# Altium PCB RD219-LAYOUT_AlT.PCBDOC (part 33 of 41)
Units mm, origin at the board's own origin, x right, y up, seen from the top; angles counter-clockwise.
Board outline 209.75 x 159.97 mm, 2 copper layers (TOP, BOTTOM), stack 0 mm thick; 398 components, 199 nets, 1469 pads, 0 vias.
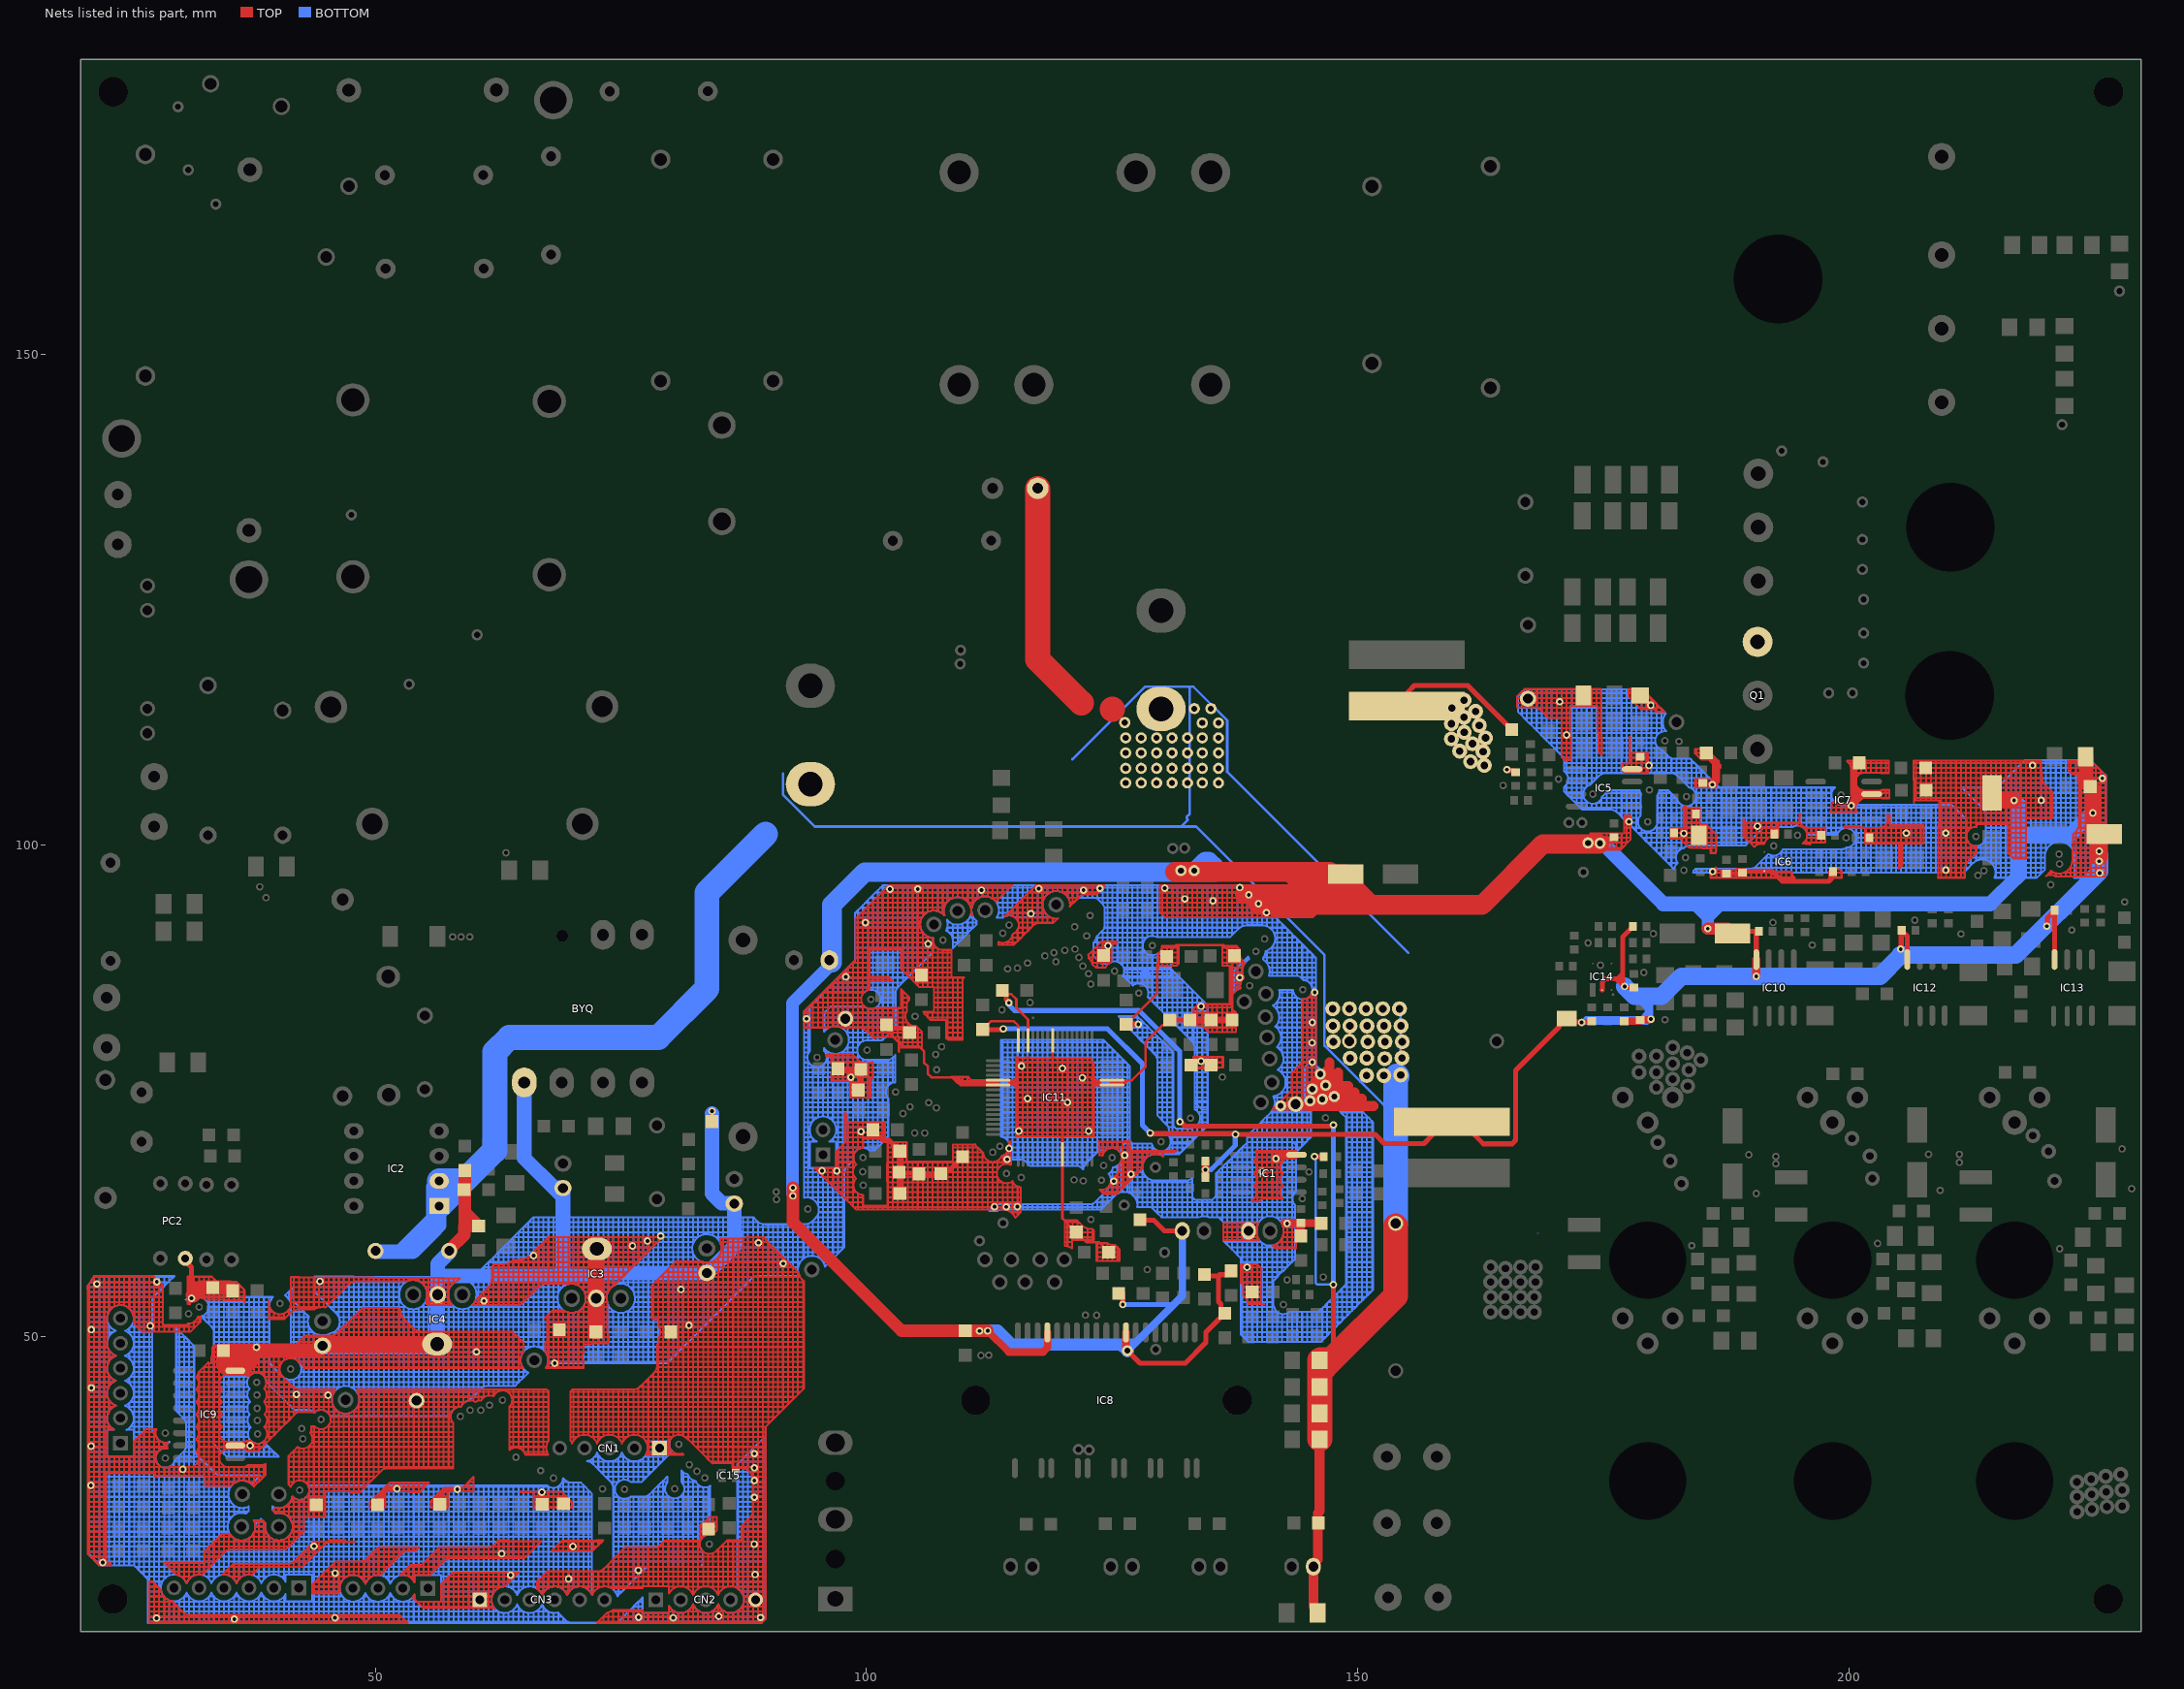
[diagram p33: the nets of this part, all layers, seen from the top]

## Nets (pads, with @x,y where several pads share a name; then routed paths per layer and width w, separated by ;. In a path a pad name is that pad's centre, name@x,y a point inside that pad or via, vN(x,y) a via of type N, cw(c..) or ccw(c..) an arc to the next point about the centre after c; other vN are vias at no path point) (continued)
GND: (continued)
  BOTTOM w0.203: 131.125,68.586 131.125,68.768 ; 131.125,68.586 131.633,68.586 ; 131.125,68.768 131.125,69.276 ; 131.125,68.768 131.252,68.641 131.633,68.641 ; 131.125,68.768 131.633,68.768 ; 131.125,69.276 131.633,69.276 ; 131.125,69.276 131.125,69.657 ; 131.125,69.657 131.125,69.784 ; 131.125,69.657 131.633,69.657 ; 131.125,69.784 131.125,70.292 ; 131.125,69.784 131.633,69.784 ; 131.125,70.292 131.125,70.8 ; 131.125,70.292 131.633,70.292 ; 131.125,70.8 131.633,70.8 ; 131.125,70.8 131.125,71.308 ; 131.125,71.308 131.125,71.816 ; 131.125,71.308 131.379,71.308 ; 131.125,71.816 131.125,72.324 ; 131.125,71.816 131.252,71.816 ; 131.125,72.324 131.125,72.832 ; 131.125,72.324 131.252,72.324 ; 131.125,72.832 131.125,73.34 ; 131.125,72.832 131.252,72.832 ; 131.125,73.34 131.125,73.848 ; 131.125,73.34 131.252,73.34 ; 131.125,73.848 131.125,74.356 ; 131.125,73.848 131.252,73.848 ; 131.125,74.356 131.125,74.864 ; 131.125,74.356 131.252,74.356 ; 131.125,74.864 131.125,75.372 ; 131.125,74.864 131.252,74.864 ; 131.125,75.372 131.125,75.88 ; 131.125,75.372 131.252,75.372 ; 131.125,75.88 131.125,76.388 ; 131.125,75.88 131.252,75.88 ; 131.125,76.388 131.125,76.896 ; 131.125,76.388 131.252,76.388 ; 131.125,76.896 131.125,77.404 ; 131.125,76.896 131.252,76.896 ; 131.125,77.404 131.125,77.912 ; 131.125,77.404 131.252,77.404 ; 131.125,77.912 131.252,77.912 ; 131.125,77.912 131.125,78.42 ; 131.125,78.42 131.252,78.42 ; 131.125,78.42 131.125,78.928 ; 131.125,78.928 131.252,78.928 ; 131.125,78.928 131.125,79.055 ; 131.125,79.055 131.252,78.928 ; 131.125,82.06 131.209,81.976 ; 131.125,82.06 131.125,82.484 ; 131.125,82.484 131.125,82.992 ; 131.125,82.484 131.633,82.484 ; 131.125,82.992 131.125,83.5 ; 131.125,82.992 131.633,82.992 ; 131.125,83.5 131.125,84.008 ; 131.125,83.5 131.633,83.5 ; 131.125,84.008 131.125,84.516 ; 131.125,84.008 131.633,84.008 ; 131.125,84.516 131.633,84.516 ; 131.125,84.516 131.125,85.024 ; 131.125,85.024 131.125,85.532 ; 131.125,85.024 131.633,85.024 ; 131.125,85.532 131.125,86.04 ; 131.125,85.532 131.633,85.532 ; 131.125,86.04 131.125,86.548 ; 131.125,86.04 131.633,86.04 ; 131.125,86.548 131.125,87.056 ; 131.125,86.548 131.633,86.548 ; 131.125,87.056 131.379,87.056 ; 131.125,87.056 131.125,87.31 ; 131.125,87.31 131.379,87.056 ; 131.125,90.655 131.125,91.12 ; 131.125,90.655 131.633,90.655 ; 131.125,91.12 131.125,91.628 ; 131.125,91.12 131.633,91.12 ; 131.125,91.628 131.125,92.136 ; 131.125,91.628 131.633,91.628 ; 131.125,92.136 131.125,92.644 ; 131.125,92.136 131.633,92.136 ; 131.125,92.644 131.125,93.152 ; 131.125,92.644 131.633,92.644 ; 131.125,93.152 131.125,93.66 ; 131.125,93.152 131.633,93.152 ; 131.125,93.66 131.125,94.168 ; 131.125,93.66 131.633,93.66 ; 131.125,94.168 131.125,94.676 ; 131.125,94.168 131.633,94.168 ; 131.125,94.676 131.125,95.184 ; 131.125,94.676 131.633,94.676 ; 131.125,95.184 131.125,95.692 ; 131.125,95.184 131.633,95.184 ; 131.125,95.692 131.125,95.946 ; 131.125,95.692 131.633,95.692 ; 131.125,95.946 131.633,95.946 ; 131.209,81.976 131.633,81.552 ; 131.209,81.976 131.633,81.976 ; 131.252,71.816 131.252,72.324 ; 131.252,71.816 131.252,71.435 131.379,71.308 ; 131.252,72.324 131.252,72.832 ; 131.252,72.832 131.252,73.34 ; 131.252,73.34 131.252,73.848 ; 131.252,73.848 131.252,74.356 ; 131.252,74.356 131.252,74.864 ; 131.252,74.864 131.252,75.372 ; 131.252,75.372 131.252,75.88 ; 131.252,75.88 131.252,76.388 ; 131.252,76.388 131.252,76.896 ; 131.252,76.896 131.252,77.404 ; 131.252,77.404 131.252,77.912 ; 131.252,77.912 131.252,78.42 ; 131.252,78.42 131.252,78.928 ; 131.379,71.308 131.506,71.181 131.633,71.181 ; 131.379,87.056 131.633,86.802 ; 131.633,62.164 131.633,62.672 ; 131.633,62.164 132.141,62.164 ; 131.633,62.672 131.633,63.18 ; 131.633,62.672 132.141,62.672 ; 131.633,63.18 131.633,63.688 ; 131.633,63.18 132.141,63.18 ; 131.633,63.688 131.633,64.196 ; 131.633,63.688 132.141,63.688 ; 131.633,64.196 131.633,64.704 ; 131.633,64.196 132.141,64.196 ; 131.633,64.704 131.633,65.212 ; 131.633,64.704 132.141,64.704 ; 131.633,65.212 131.633,65.72 ; 131.633,65.212 132.141,65.212 ; 131.633,65.72 131.633,65.882 ; 131.633,65.72 132.141,65.72 ; 131.633,65.882 132.141,65.882 ; 131.633,68.586 131.633,68.641 ; 131.633,68.586 131.832,68.586 132.713,69.466 ; 131.633,68.641 131.633,68.768 ; 131.633,68.641 131.887,68.641 132.014,68.768 ; 131.633,68.768 131.633,69.276 ; 131.633,68.768 132.014,68.768 ; 131.633,69.276 132.141,69.276 ; 131.633,69.276 131.633,69.657 ; 131.633,69.657 131.633,69.784 ; 131.633,69.657 132.141,69.657 ; 131.633,69.784 131.633,70.292 ; 131.633,69.784 132.141,69.784 ; 131.633,70.292 131.633,70.8 ; 131.633,70.292 132.141,70.292 ; 131.633,70.8 132.141,70.8 ; 131.633,70.8 131.633,71.181 ; 131.633,71.181 132.141,71.181 ; 131.633,81.552 131.717,81.468 ; 131.633,81.552 131.633,81.976 ; 131.633,81.976 131.633,82.484 ; 131.633,81.976 132.141,81.976 ; 131.633,82.484 131.633,82.992 ; 131.633,82.484 132.141,82.484 ; 131.633,82.992 131.633,83.5 ; 131.633,82.992 132.141,82.992 ; 131.633,83.5 131.633,84.008 ; 131.633,83.5 132.141,83.5 ; 131.633,84.008 131.633,84.516 ; 131.633,84.008 132.141,84.008 ; 131.633,84.516 131.633,85.024 ; 131.633,84.516 132.141,84.516 ; 131.633,85.024 131.633,85.532 ; 131.633,85.024 132.141,85.024 ; 131.633,85.532 131.633,86.04 ; 131.633,85.532 132.141,85.532 ; 131.633,86.04 131.633,86.548 ; 131.633,86.04 132.141,86.04 ; 131.633,86.548 131.633,86.802 ; 131.633,86.548 131.887,86.548 ; 131.633,86.802 131.887,86.548 ; 131.633,90.655 131.633,91.12 ; 131.633,90.655 132.141,90.655 ; 131.633,91.12 131.633,91.628 ; 131.633,91.12 132.141,91.12 ; 131.633,91.628 131.633,92.136 ; 131.633,91.628 132.141,91.628 ; 131.633,92.136 131.633,92.644 ; 131.633,92.136 132.141,92.136 ; 131.633,92.644 131.633,93.152 ; 131.633,92.644 132.141,92.644 ; 131.633,93.152 131.633,93.66 ; 131.633,93.152 132.141,93.152 ; 131.633,93.66 131.633,94.168 ; 131.633,93.66 132.141,93.66 ; 131.633,94.168 131.633,94.676 ; 131.633,94.168 132.141,94.168 ; 131.633,94.676 131.633,95.184 ; 131.633,94.676 pad.@132.141,94.676 ; 131.633,95.184 131.633,95.692 ; 131.633,95.184 132.141,95.184 ; 131.633,95.692 131.633,95.946 ; 131.633,95.692 132.141,95.692 ; 131.633,95.946 132.141,95.946 ; 131.717,81.468 132.141,81.044 ; 131.717,81.468 132.141,81.468 ; 131.887,86.548 132.141,86.294 ; 132.014,68.768 132.141,68.895 ; 132.141,62.164 132.141,62.672 ; 132.141,62.164 132.649,62.164 ; 132.141,62.672 132.141,63.18 ; 132.141,62.672 132.649,62.672 ; 132.141,63.18 132.141,63.688 ; 132.141,63.18 132.649,63.18 ; 132.141,63.688 132.141,64.196 ; 132.141,63.688 132.649,63.688 ; 132.141,64.196 132.141,64.704 ; 132.141,64.196 132.649,64.196 ; 132.141,64.704 132.141,65.212 ; 132.141,64.704 132.649,64.704 ; 132.141,65.212 132.141,65.72 ; 132.141,65.212 132.649,65.212 ; 132.141,65.72 132.141,65.882 ; 132.141,65.72 132.649,65.72 ; 132.141,65.882 132.392,65.882 ; 132.141,68.895 132.649,69.403 ; 132.141,68.895 132.141,69.276 ; 132.141,69.276 132.141,69.657 ; 132.141,69.657 132.141,69.784 ; 132.141,69.657 132.522,69.657 132.649,69.53 ; 132.141,69.784 132.141,70.292 ; 132.141,69.784 132.649,69.784 ; 132.141,70.292 132.141,70.8 ; 132.141,70.292 132.649,70.292 ; 132.141,70.8 132.649,70.8 ; 132.141,70.8 132.141,71.181 ; 132.141,71.181 132.649,71.181 ; 132.141,81.044 132.225,80.96 ; 132.141,81.044 132.141,81.468 ; 132.141,81.468 132.141,81.976 ; 132.141,81.468 132.649,81.468 ; 132.141,81.976 132.141,82.484 ; 132.141,81.976 132.649,81.976 ; 132.141,82.484 132.141,82.992 ; 132.141,82.484 132.649,82.484 ; 132.141,82.992 132.141,83.5 ; 132.141,82.992 132.649,82.992 ; 132.141,83.5 132.141,84.008 ; 132.141,83.5 132.649,83.5 ; 132.141,84.008 132.141,84.516 ; 132.141,84.008 132.649,84.008 ; 132.141,84.516 132.141,85.024 ; 132.141,84.516 132.649,84.516 ; 132.141,85.024 132.141,85.532 ; 132.141,85.024 132.649,85.024 ; 132.141,85.532 132.141,86.04 ; 132.141,85.532 132.649,85.532 ; 132.141,86.04 132.141,86.294 ; 132.141,86.04 132.395,86.04 ; 132.141,86.294 132.395,86.04 ; 132.141,90.655 132.141,91.12 ; 132.141,90.655 132.649,90.655 ; 132.141,91.12 132.141,91.628 ; 132.141,91.12 132.649,91.12 ; 132.141,91.628 132.141,92.136 ; 132.141,91.628 132.649,91.628 ; 132.141,92.136 132.141,92.644 ; 132.141,92.136 132.649,92.136 ; 132.141,92.644 132.141,93.152 ; 132.141,92.644 132.649,92.644 ; 132.141,93.152 132.141,93.66 ; 132.141,93.152 132.649,93.152 ; 132.141,93.66 132.141,94.168 ; 132.141,93.66 132.649,93.66 ; 132.141,94.168 pad.@132.141,94.676 ; 132.141,94.168 132.649,94.168 ; pad.@132.141,94.676 132.141,95.184 ; pad.@132.141,94.676 pad.@132.649,94.676 ; 132.141,95.184 132.141,95.692 ; 132.141,95.184 132.649,95.184 ; 132.141,95.692 132.141,95.946 ; 132.141,95.692 132.649,95.692 ; 132.141,95.946 132.649,95.946 ; 132.225,80.96 132.649,80.536 ; 132.225,80.96 132.649,80.96 ; 132.392,65.882 ccw(c132.392,67.234) 132.649,65.907 ; 132.392,65.882 ccw(c132.392,67.234) 132.649,65.907 ; 132.395,86.04 132.649,85.786 ; 132.649,62.164 133.157,62.164 ; 132.649,62.164 132.649,62.672 ; 132.649,62.672 133.157,62.672 ; 132.649,62.672 132.649,63.18 ; 132.649,63.18 133.157,63.18 ; 132.649,63.18 132.649,63.688 ; 132.649,63.688 132.649,64.196 ; 132.649,63.688 133.157,63.688 ; 132.649,64.196 133.157,64.196 ; 132.649,64.196 132.649,64.704 ; 132.649,64.704 133.157,64.704 ; 132.649,64.704 132.649,65.212 ; 132.649,65.212 133.157,65.212 ; 132.649,65.212 132.649,65.72 ; 132.649,65.72 133.157,65.72 ; 132.649,65.72 132.649,65.907 ; 132.649,69.403 132.713,69.466 ; 132.649,69.403 132.649,69.53 ; 132.649,69.53 132.649,69.784 ; 132.649,69.53 132.713,69.466 ; 132.649,69.784 132.649,70.292 ; 132.649,70.292 132.649,70.8 ; 132.649,70.292 133.157,70.292 ; 132.649,70.8 133.157,70.8 ; 132.649,70.8 132.649,71.181 ; 132.649,80.536 132.733,80.452 ; 132.649,80.536 132.649,80.96 ; 132.649,80.96 133.157,80.96 ; 132.649,80.96 132.649,81.468 ; 132.649,81.468 133.157,81.468 ; 132.649,81.468 132.649,81.976 ; 132.649,81.976 133.157,81.976 ; 132.649,81.976 132.649,82.484 ; 132.649,82.484 133.157,82.484 ; 132.649,82.484 132.649,82.992 ; 132.649,82.992 133.157,82.992 ; 132.649,82.992 132.649,83.5 ; 132.649,83.5 132.649,84.008 ; 132.649,83.5 133.157,83.5 ; 132.649,84.008 132.649,84.516 ; 132.649,84.008 133.157,84.008 ; 132.649,84.516 133.157,84.516 ; 132.649,84.516 132.649,85.024 ; 132.649,85.024 132.649,85.532 ; 132.649,85.024 133.157,85.024 ; 132.649,85.532 132.649,85.786 ; 132.649,85.532 132.903,85.532 ; 132.649,85.786 132.903,85.532 ; 132.649,90.655 132.649,91.12 ; 132.649,90.655 133.157,90.655 ; 132.649,91.12 132.649,91.628 ; 132.649,91.12 133.157,91.12 ; 132.649,91.628 132.649,92.136 ; 132.649,91.628 133.157,91.628 ; 132.649,92.136 132.649,92.644 ; 132.649,92.136 133.157,92.136 ; 132.649,92.644 132.649,93.152 ; 132.649,92.644 133.157,92.644 ; 132.649,93.152 132.649,93.66 ; 132.649,93.152 133.157,93.152 ; 132.649,93.66 132.649,94.168 ; 132.649,93.66 133.157,93.66 ; 132.649,94.168 133.157,94.168 ; 132.649,94.168 pad.@132.649,94.676 ; pad.@132.649,94.676 132.649,95.184 ; pad.@132.649,94.676 133.157,94.676 ; 132.649,95.184 132.649,95.692 ; 132.649,95.184 133.157,95.184 ; 132.649,95.692 132.649,95.946 ; 132.649,95.692 133.157,95.692 ; 132.649,95.946 133.157,95.946 ; 132.713,69.466 134.726,71.48 134.726,71.816 ; 132.733,80.452 133.157,80.452 ; 132.903,85.532 133.157,85.278 ; 133.157,62.164 133.665,62.164 ; 133.157,62.164 133.157,62.672 ; 133.157,62.672 133.665,62.672 ; 133.157,62.672 133.157,63.18 ; 133.157,63.18 133.665,63.18 ; 133.157,63.18 133.157,63.688 ; 133.157,63.688 133.157,64.196 ; 133.157,63.688 133.665,63.688 ; 133.157,64.196 133.157,64.704 ; 133.157,64.196 133.157,64.704 ; 133.157,64.196 133.411,63.942 133.665,63.942 ; 133.157,64.704 133.157,65.212 ; 133.157,64.704 133.157,65.212 ; 133.157,65.212 133.157,65.72 ; 133.157,65.212 133.157,65.72 ; 133.157,65.72 133.157,66.12 ; 133.157,65.72 133.157,66.12 ; 133.157,66.12 cw(c132.392,67.234) 132.65,65.907 ccw(c132.392,67.234) 133.157,66.12 ; 133.157,66.12 ccw(c132.392,67.234) 133.167,66.127 cw(c132.392,67.234) 133.157,66.12 ; 133.157,70.292 133.157,70.8 ; 133.157,70.8 133.665,70.8 ; 133.157,70.8 133.157,71.28 ; 133.157,71.28 ccw(c132.977,72.246) 133.269,71.308 ; 133.157,80.452 133.157,80.96 ; 133.157,80.452 133.157,80.026 133.157,80.452 ; 133.157,80.452 133.157,80.96 ; 133.157,80.96 133.157,81.468 ; 133.157,80.96 133.157,81.468 ; 133.157,81.468 133.157,81.976 ; 133.157,81.468 133.157,81.976 ; 133.157,81.976 133.157,82.484 ; 133.157,81.976 133.157,82.484 ; 133.157,82.484 133.157,82.992 ; 133.157,82.484 133.157,82.992 ; 133.157,82.992 133.157,83.5 ; 133.157,82.992 133.284,83.119 ; 133.157,83.5 133.157,84.008 ; 133.157,83.5 133.665,83.5 ; 133.157,84.008 133.157,84.516 ; 133.157,84.008 133.665,84.008 ; 133.157,84.516 133.665,84.516 ; 133.157,84.516 133.157,85.024 ; 133.157,85.024 133.157,85.278 ; 133.157,85.024 133.411,85.024 ; 133.157,85.278 133.411,85.024 ; 133.157,90.655 133.157,91.12 ; 133.157,90.655 133.665,90.655 ; 133.157,91.12 133.157,91.628 ; 133.157,91.12 133.665,91.12 ; 133.157,91.628 133.157,92.136 ; 133.157,91.628 133.665,91.628 ; 133.157,92.136 133.157,92.644 ; 133.157,92.136 133.665,92.136 ; 133.157,92.644 133.157,93.152 ; 133.157,92.644 133.665,92.644 ; 133.157,93.152 133.157,93.66 ; 133.157,93.152 133.665,93.152 ; 133.157,93.66 133.157,94.168 ; 133.157,93.66 133.665,93.66 ; 133.157,94.168 133.157,94.676 ; 133.157,94.168 133.665,94.168 ; 133.157,94.676 133.157,95.184 ; 133.157,94.676 133.665,94.676 ; 133.157,95.184 133.157,95.692 ; 133.157,95.184 133.665,95.184 ; 133.157,95.692 133.157,95.946 ; 133.157,95.692 133.665,95.692 ; 133.157,95.946 133.665,95.946 ; 133.269,71.308 ccw(c132.977,72.246) 133.665,71.545 ; 133.269,71.308 133.665,71.308 ; 133.284,79.944 133.284,80.452 ; 133.284,79.944 133.665,79.944 ; 133.284,80.452 133.665,80.452 ; 133.284,80.452 133.284,80.96 ; 133.284,80.96 133.665,80.96 ; 133.284,80.96 133.284,81.468 ; 133.284,81.468 133.284,81.976 ; 133.284,81.468 133.665,81.468 ; 133.284,81.976 133.284,82.484 ; 133.284,81.976 133.665,81.976 ; 133.284,82.484 133.284,82.992 ; 133.284,82.484 133.665,82.484 ; 133.284,82.992 133.284,83.119 ; 133.284,82.992 133.665,82.992 ; 133.284,83.119 133.665,83.119 ; 133.411,85.024 133.665,84.77 ; 133.423,79.436 cw(c132.573,79.339) 133.429,79.339 ; 133.423,79.436 cw(c132.573,79.339) 133.429,79.339 ; 133.423,79.436 ccw(c132.573,79.339) 133.328,79.741 cw(c132.573,79.339) 133.423,79.436 ; 133.423,79.436 133.665,79.436 ; 133.429,73.118 cw(c132.977,72.246) 133.665,72.947 ; 133.429,73.118 133.429,73.34 ; 133.429,73.34 133.429,73.83 ; 133.429,73.34 133.665,73.34 ; 133.429,73.83 133.429,73.848 ; 133.429,73.83 133.665,73.594 ; 133.429,73.848 133.429,73.975 ; 133.429,73.848 133.665,73.848 ; 133.429,73.975 133.429,74.356 ; 133.429,73.975 133.665,73.975 ; 133.429,74.356 133.665,74.356 ; 133.429,74.356 133.429,74.864 ; 133.429,74.864 133.665,74.864 ; 133.429,74.864 133.429,75.372 ; 133.429,75.372 133.665,75.372 ; 133.429,75.372 133.429,75.88 ; 133.429,75.88 133.665,75.88 ; 133.429,75.88 133.429,76.388 ; 133.429,76.388 133.665,76.388 ; 133.429,76.388 133.429,76.896 ; 133.429,76.896 133.665,76.896 ; 133.429,76.896 133.429,77.404 ; 133.429,77.404 133.665,77.404 ; 133.429,77.404 133.429,77.912 ; 133.429,77.912 133.665,77.912 ; 133.429,77.912 133.429,78.42 ; 133.429,78.42 133.665,78.42 ; 133.429,78.42 133.429,78.928 ; 133.429,78.928 133.665,78.928 ; 133.429,78.928 133.429,79.339 ; 133.665,62.164 133.665,62.672 ; 133.665,62.164 133.82,62.164 ; 133.665,62.672 134.173,62.672 ; 133.665,62.672 133.665,63.18 ; 133.665,63.18 134.173,63.18 ; 133.665,63.18 133.665,63.688 ; 133.665,63.688 133.665,63.942 ; 133.665,63.688 134.173,63.688 ; 133.665,63.942 134.173,63.942 ; 133.665,70.8 133.665,71.308 ; 133.665,71.308 134.173,71.308 ; 133.665,71.308 133.665,71.545 ; 133.665,72.947 cw(c132.977,72.246) 133.761,72.837 cw(c132.977,72.246) 133.765,72.832 ; 133.665,72.947 133.665,73.34 ; 133.665,73.34 133.665,73.594 ; 133.665,73.34 133.919,73.34 ; 133.665,73.594 133.665,73.848 ; 133.665,73.594 133.919,73.34 ; 133.665,73.848 134.173,73.848 ; 133.665,73.848 133.665,73.975 ; 133.665,73.975 134.173,73.975 ; 133.665,73.975 133.665,74.356 ; 133.665,74.356 133.665,74.864 ; 133.665,74.356 134.173,74.356 ; 133.665,74.864 133.665,75.372 ; 133.665,74.864 134.173,74.864 ; 133.665,75.372 133.665,75.88 ; 133.665,75.372 134.173,75.372 ; 133.665,75.88 133.665,76.388 ; 133.665,75.88 134.173,75.88 ; 133.665,76.388 133.665,76.896 ; 133.665,76.388 134.173,76.388 ; 133.665,76.896 133.665,77.404 ; 133.665,76.896 134.173,76.896 ; 133.665,77.404 133.665,77.912 ; 133.665,77.404 134.173,77.404 ; 133.665,77.912 pad.@134.173,77.912 ; 133.665,77.912 133.665,78.42 ; 133.665,78.42 133.665,78.928 ; 133.665,78.42 134.173,78.42 ; 133.665,78.928 133.665,79.436 ; 133.665,78.928 134.173,78.928 ; 133.665,79.436 134.173,79.436 ; 133.665,79.436 133.665,79.944 ; 133.665,79.944 134.173,79.944 ; 133.665,79.944 133.665,80.452 ; 133.665,80.452 133.665,80.96 ; 133.665,80.452 134.173,80.452 ; 133.665,80.96 133.665,81.468 ; 133.665,80.96 134.173,80.96 ; 133.665,81.468 133.665,81.976 ; 133.665,81.468 134.173,81.468 ; 133.665,81.976 134.173,81.976 ; 133.665,81.976 133.665,82.484 ; 133.665,82.484 133.665,82.992 ; 133.665,82.484 134.173,82.484 ; 133.665,82.992 134.173,82.992 ; 133.665,82.992 133.665,83.119 ; 133.665,83.119 134.173,83.119 ; 133.665,83.119 134.173,83.119 ; 133.665,83.119 133.665,83.5 ; 133.665,83.5 133.665,84.008 ; 133.665,83.5 pad.@134.173,83.5 ; 133.665,84.008 133.665,84.516 ; 133.665,84.008 134.173,84.008 ; 133.665,84.516 133.665,84.77 ; 133.665,84.516 133.919,84.516 ; 133.665,84.77 133.919,84.516 ; 133.665,90.655 133.665,91.12 ; 133.665,90.655 134.173,90.655 ; 133.665,91.12 133.665,91.628 ; 133.665,91.12 134.173,91.12 ; 133.665,91.628 133.665,92.136 ; 133.665,91.628 134.173,91.628 ; 133.665,92.136 133.665,92.644 ; 133.665,92.136 134.173,92.136 ; 133.665,92.644 133.665,93.152 ; 133.665,92.644 134.173,92.644 ; 133.665,93.152 133.665,93.66 ; 133.665,93.152 134.173,93.152 ; 133.665,93.66 133.665,94.168 ; 133.665,93.66 134.173,93.66 ; 133.665,94.168 133.665,94.676 ; 133.665,94.168 134.173,94.168 ; 133.665,94.676 133.665,95.184 ; 133.665,94.676 134.173,94.676 ; 133.665,95.184 133.665,95.692 ; 133.665,95.184 134.173,95.184 ; 133.665,95.692 133.665,95.946 ; 133.665,95.692 134.173,95.692 ; 133.665,95.946 134.173,95.946 ; 133.765,72.832 cw(c132.977,72.246) 133.956,72.324 ; 133.765,72.832 134.173,72.832 ; 133.82,62.164 cw(c134.341,60.917) 134.173,62.258 ; 133.919,73.34 134.173,73.086 ; 133.919,73.34 134.173,73.34 ; 133.919,84.516 134.173,84.262 ; 133.956,72.324 cw(c132.977,72.246) 133.959,72.246 cw(c132.977,72.246) 133.86,71.816 134.173,71.816 ; 133.956,72.324 134.173,72.324 ; 134.173,62.258 cw(c134.341,60.917) 134.176,62.259 cw(c134.341,60.917) 134.681,62.225 ; 134.173,62.258 134.173,62.672 ; 134.173,62.672 134.681,62.672 ; 134.173,62.672 134.173,63.18 ; 134.173,63.18 134.681,63.18 ; 134.173,63.18 134.173,63.688 ; 134.173,63.688 134.173,63.942 ; 134.173,63.688 134.681,63.688 ; 134.173,63.942 134.681,63.942 ; 134.173,71.308 134.173,71.816 ; 134.173,71.816 134.173,72.324 ; 134.173,71.816 134.681,71.816 ; 134.173,72.324 134.681,72.324 ; 134.173,72.324 134.173,72.832 ; 134.173,72.832 134.173,73.086 ; 134.173,72.832 134.681,72.832 ; 134.173,73.086 134.681,73.086 ; 134.173,73.086 134.173,73.34 ; 134.173,73.34 134.173,73.848 ; 134.173,73.34 134.681,73.34 ; 134.173,73.848 134.173,73.975 ; 134.173,73.848 134.681,73.848 ; 134.173,73.975 134.681,73.975 ; 134.173,73.975 134.173,74.356 ; 134.173,74.356 134.173,74.864 ; 134.173,74.356 134.681,74.356 ; 134.173,74.864 134.173,75.372 ; 134.173,74.864 134.681,74.864 ; 134.173,75.372 134.173,75.88 ; 134.173,75.372 134.681,75.372 ; 134.173,75.88 134.173,76.388 ; 134.173,75.88 134.681,75.88 ; 134.173,76.388 134.173,76.896 ; 134.173,76.388 134.681,76.388 ; 134.173,76.896 134.173,77.404 ; 134.173,76.896 134.681,76.896 ; 134.173,77.404 pad.@134.173,77.912 ; 134.173,77.404 134.681,77.404 ; pad.@134.173,77.912 134.681,77.912 ; pad.@134.173,77.912 134.173,78.42 ; 134.173,78.42 134.173,78.928 ; 134.173,78.42 134.681,78.42 ; 134.173,78.928 134.173,79.436 ; 134.173,78.928 134.681,78.928 ; 134.173,79.436 134.681,79.436 ; 134.173,79.436 134.173,79.944 ; 134.173,79.944 134.681,79.944 ; 134.173,79.944 134.173,80.452 ; 134.173,80.452 134.173,80.96 ; 134.173,80.452 134.681,80.452 ; 134.173,80.96 134.173,81.468 ; 134.173,80.96 134.681,80.96 ; 134.173,81.468 134.173,81.976 ; 134.173,81.468 134.681,81.468 ; 134.173,81.976 134.681,81.976 ; 134.173,81.976 134.173,82.484 ; 134.173,82.484 134.173,82.992 ; 134.173,82.484 134.681,82.484 ; 134.173,82.992 134.681,82.992 ; 134.173,82.992 134.173,83.119 ; 134.173,83.119 134.681,83.119 ; 134.173,83.119 134.681,83.119 ; 134.173,83.119 pad.@134.173,83.5 ; pad.@134.173,83.5 134.681,83.5 ; pad.@134.173,83.5 134.173,84.008 ; 134.173,84.008 134.173,84.262 ; 134.173,84.008 134.427,84.008 ; 134.173,84.262 134.427,84.008 ; 134.173,90.655 134.173,91.12 ; 134.173,90.655 134.681,90.655 ; 134.173,91.12 134.173,91.628 ; 134.173,91.12 134.681,91.12 ; 134.173,91.628 134.173,92.136 ; 134.173,91.628 134.681,91.628 ; 134.173,92.136 134.173,92.644 ; 134.173,92.136 134.681,92.136 ; 134.173,92.644 134.173,93.152 ; 134.173,92.644 134.681,92.644 ; 134.173,93.152 134.173,93.66 ; 134.173,93.152 134.681,93.152 ; 134.173,93.66 134.173,94.168 ; 134.173,93.66 134.681,93.66 ; 134.173,94.168 134.173,94.676 ; 134.173,94.168 134.681,94.168 ; 134.173,94.676 134.173,95.184 ; 134.173,94.676 134.681,94.676 ; 134.173,95.184 134.173,95.692 ; 134.173,95.184 134.681,95.184 ; 134.173,95.692 134.173,95.946 ; 134.173,95.692 134.681,95.692 ; 134.173,95.946 134.681,95.946 ; 134.427,84.008 134.681,83.754 ; 134.681,62.225 cw(c134.341,60.917) 134.862,62.164 ; 134.681,62.225 134.681,62.672 ; 134.681,62.672 135.189,62.672 ; 134.681,62.672 134.681,63.18 ; 134.681,63.18 135.189,63.18 ; 134.681,63.18 134.681,63.688 ; 134.681,63.688 134.681,63.942 ; 134.681,63.688 135.189,63.688 ; 134.681,63.942 135.189,63.942 ; 134.681,71.816 134.681,72.324 ; 134.681,71.816 134.726,71.816 ; 134.681,72.324 134.726,72.324 ; 134.681,72.324 134.681,72.832 ; 134.681,72.832 134.681,73.086 ; 134.681,72.832 134.726,72.832 ; 134.681,73.086 134.681,73.34 ; 134.681,73.086 134.726,73.086 ; 134.681,73.34 134.681,73.848 ; 134.681,73.34 134.726,73.34 ; 134.681,73.848 134.681,73.975 ; 134.681,73.848 134.726,73.848 ; 134.681,73.975 134.681,74.356 ; 134.681,73.975 134.726,73.975 ; 134.681,74.356 134.681,74.864 ; 134.681,74.356 134.726,74.356 ; 134.681,74.864 134.681,75.372 ; 134.681,74.864 134.726,74.864 ; 134.681,75.372 134.681,75.88 ; 134.681,75.372 134.726,75.372 ; 134.681,75.88 134.681,76.388 ; 134.681,75.88 134.726,75.88 ; 134.681,76.388 134.681,76.896 ; 134.681,76.388 134.726,76.388 ; 134.681,76.896 134.681,77.404 ; 134.681,76.896 134.726,76.896 ; 134.681,77.404 134.681,77.912 ; 134.681,77.404 134.726,77.404 ; 134.681,77.912 134.681,78.42 ; 134.681,77.912 134.726,77.912 ; 134.681,78.42 134.681,78.928 ; 134.681,78.42 134.726,78.42 ; 134.681,78.928 134.681,79.436 ; 134.681,78.928 134.726,78.928 ; 134.681,79.436 134.726,79.436 ; 134.681,79.436 134.681,79.944 ; 134.681,79.944 134.726,79.944 ; 134.681,79.944 134.681,80.452 ; 134.681,80.452 134.681,80.96 ; 134.681,80.452 134.726,80.452 ; 134.681,80.96 134.681,81.468 ; 134.681,80.96 134.726,80.96 ; 134.681,81.468 134.681,81.976 ; 134.681,81.468 134.726,81.468 ; 134.681,81.976 134.726,81.976 ; 134.681,81.976 134.681,82.484 ; 134.681,82.484 134.681,82.992 ; 134.681,82.484 134.726,82.484 ; 134.681,82.992 134.726,82.992 ; 134.681,82.992 134.681,83.119 ; 134.681,83.119 134.726,83.119 ; 134.681,83.119 134.726,83.119 ; 134.681,83.119 134.681,83.5 ; 134.681,83.5 134.681,83.754 ; 134.681,83.5 134.726,83.5 ; 134.681,83.754 134.726,83.709 134.726,83.5 ; 134.681,90.655 134.681,91.12 ; 134.681,90.655 135.189,90.655 ; 134.681,91.12 134.681,91.628 ; 134.681,91.12 135.189,91.12 ; 134.681,91.628 134.681,92.136 ; 134.681,91.628 135.189,91.628 ; 134.681,92.136 134.681,92.644 ; 134.681,92.136 135.189,92.136 ; 134.681,92.644 134.681,93.152 ; 134.681,92.644 135.189,92.644 ; 134.681,93.152 134.681,93.66 ; 134.681,93.152 135.189,93.152 ; 134.681,93.66 134.681,94.168 ; 134.681,93.66 135.189,93.66 ; 134.681,94.168 134.681,94.676 ; 134.681,94.168 pad.@135.189,94.168 ; 134.681,94.676 134.681,95.184 ; 134.681,94.676 pad.@135.189,94.676 ; 134.681,95.184 134.681,95.692 ; 134.681,95.184 135.189,95.184 ; 134.681,95.692 134.681,95.946 ; 134.681,95.692 135.189,95.692 ; 134.681,95.946 135.189,95.946 ; 134.726,71.816 134.726,72.324 ; 134.726,72.324 134.726,72.832 ; 134.726,72.832 134.726,73.086 ; 134.726,73.086 134.726,73.34 ; 134.726,73.34 134.726,73.848 ; 134.726,73.848 134.726,73.975 ; 134.726,73.975 134.726,74.356 ; 134.726,74.356 134.726,74.864 ; 134.726,74.864 134.726,75.372 ; 134.726,75.372 134.726,75.88 ; 134.726,75.88 134.726,76.388 ; 134.726,76.388 134.726,76.896 ; 134.726,76.896 134.726,77.404 ; 134.726,77.404 134.726,77.912 ; 134.726,77.912 134.726,78.42 ; 134.726,78.42 134.726,78.928 ; 134.726,78.928 134.726,79.436 ; 134.726,79.436 134.726,79.944 ; 134.726,79.944 134.726,80.452 ; 134.726,80.452 134.726,80.96 ; 134.726,80.96 134.726,81.468 ; 134.726,81.468 134.726,81.976 ; 134.726,81.976 134.726,82.484 ; 134.726,82.484 134.726,82.992 ; 134.726,82.992 134.726,83.119 ; 134.726,83.119 134.726,83.5 ; 134.862,62.164 135.189,62.164 ; 135.189,62.164 135.189,62.672 ; 135.189,62.164 135.697,62.164 ; 135.189,62.672 135.697,62.672 ; 135.189,62.672 135.189,63.18 ; 135.189,63.18 135.697,63.18 ; 135.189,63.18 135.189,63.688 ; 135.189,63.688 135.189,63.942 ; 135.189,63.688 135.697,63.688 ; 135.189,63.942 135.443,64.196 ; 135.189,90.655 135.189,91.12 ; 135.189,90.655 135.697,90.655 ; 135.189,91.12 135.189,91.628 ; 135.189,91.12 135.697,91.12 ; 135.189,91.628 135.189,92.136 ; 135.189,91.628 135.697,91.628 ; 135.189,92.136 135.189,92.644 ; 135.189,92.136 135.697,92.136 ; 135.189,92.644 135.189,93.152 ; 135.189,92.644 135.697,92.644 ; 135.189,93.152 135.189,93.66 ; 135.189,93.152 135.697,93.152 ; 135.189,93.66 pad.@135.189,94.168 ; 135.189,93.66 135.697,93.66 ; pad.@135.189,94.168 pad.@135.189,94.676 ; pad.@135.189,94.168 135.697,94.168 ; pad.@135.189,94.676 135.189,95.184 ; pad.@135.189,94.676 135.697,94.676 ; 135.189,95.184 135.189,95.692 ; 135.189,95.184 135.697,95.184 ; 135.189,95.692 135.189,95.946 ; 135.189,95.692 135.697,95.692 ; 135.189,95.946 135.697,95.946 ; 135.443,64.196 135.697,64.196 ; 135.443,64.196 135.57,64.323 135.57,64.704 ; 135.57,64.704 135.697,64.704 ; 135.57,64.704 135.57,65.212 ; 135.57,65.212 135.697,65.212 ; 135.57,65.212 135.57,65.72 ; 135.57,65.72 135.697,65.72 ; 135.57,65.72 135.57,66.228 ; 135.57,66.228 135.57,66.609 135.697,66.736 ; 135.57,66.228 135.697,66.228 ; 135.697,62.164 135.697,62.672 ; 135.697,62.164 135.824,62.164 ; 135.697,62.672 136.205,62.672 ; 135.697,62.672 135.697,63.18 ; 135.697,63.18 136.205,63.18 ; 135.697,63.18 135.697,63.688 ; 135.697,63.688 135.697,64.196 ; 135.697,63.688 136.205,63.688 ; 135.697,64.196 136.205,64.196 ; 135.697,64.196 135.697,64.704 ; 135.697,64.704 136.205,64.704 ; 135.697,64.704 135.697,65.212 ; 135.697,65.212 135.697,65.72 ; 135.697,65.212 136.205,65.212 ; 135.697,65.72 135.697,66.228 ; 135.697,65.72 136.205,65.72 ; 135.697,66.228 135.697,66.736 ; 135.697,66.228 136.205,66.228 ; 135.697,66.736 136.205,66.736 ; 135.697,66.736 136.205,67.244 ; 135.697,90.655 135.697,91.12 ; 135.697,90.655 136.205,90.655 ; 135.697,91.12 135.697,91.628 ; 135.697,91.12 136.205,91.12 ; 135.697,91.628 135.697,92.136 ; 135.697,91.628 136.205,91.628 ; 135.697,92.136 135.697,92.644 ; 135.697,92.136 136.205,92.136 ; 135.697,92.644 135.697,93.152 ; 135.697,92.644 136.205,92.644 ; 135.697,93.152 135.697,93.66 ; 135.697,93.152 136.205,93.152 ; 135.697,93.66 135.697,94.168 ; 135.697,93.66 136.205,93.66 ; 135.697,94.168 136.205,94.168 ; 135.697,94.168 135.697,94.676 ; 135.697,94.676 135.697,95.184 ; 135.697,94.676 136.205,94.676 ; 135.697,95.184 135.697,95.692 ; 135.697,95.184 136.205,95.184 ; 135.697,95.692 135.697,95.946 ; 135.697,95.692 136.205,95.692 ; 135.697,95.946 136.205,95.946 ; 135.824,62.164 136.205,62.164 ; 135.824,62.164 136.205,61.783 ; 136.205,61.783 136.205,62.164 ; 136.205,61.783 136.332,61.656 ; 136.205,62.164 136.713,62.164 ; 136.205,62.164 136.205,62.672 ; 136.205,62.672 136.713,62.672 ; 136.205,62.672 136.205,63.18 ; 136.205,63.18 136.713,63.18 ; 136.205,63.18 136.205,63.688 ; 136.205,63.688 136.205,64.196 ; 136.205,63.688 136.713,63.688 ; 136.205,64.196 136.205,64.704 ; 136.205,64.196 136.713,64.196 ; 136.205,64.704 136.713,64.704 ; 136.205,64.704 136.205,65.212 ; 136.205,65.212 136.205,65.72 ; 136.205,65.212 136.713,65.212 ; 136.205,65.72 136.205,66.228 ; 136.205,65.72 136.713,65.72 ; 136.205,66.228 136.205,66.736 ; 136.205,66.228 136.713,66.228 ; 136.205,66.736 136.713,66.736 ; 136.205,66.736 136.205,67.244 ; 136.205,67.244 136.713,67.244 ; 136.205,67.244 136.713,67.752 ; 136.205,90.655 136.713,90.655 ; 136.205,90.655 136.205,91.12 ; 136.205,91.12 136.205,91.628 ; 136.205,91.12 136.713,91.12 ; 136.205,91.628 136.205,92.136 ; 136.205,91.628 136.713,91.628 ; 136.205,92.136 136.205,92.644 ; 136.205,92.136 136.713,92.136 ; 136.205,92.644 136.205,93.152 ; 136.205,92.644 136.713,92.644 ; 136.205,93.152 136.713,93.152 ; 136.205,93.152 136.205,93.66 ; 136.205,93.66 136.713,93.66 ; 136.205,93.66 136.205,94.168 ; 136.205,94.168 136.713,94.168 ; 136.205,94.168 136.205,94.676 ; 136.205,94.676 136.713,94.676 ; 136.205,94.676 136.205,95.184 ; 136.205,95.184 136.713,95.184 ; 136.205,95.184 136.205,95.692 ; 136.205,95.692 136.713,95.692 ; 136.205,95.692 136.205,95.946 ; 136.205,95.946 136.713,95.946 ; 136.332,60.132 136.713,60.132 ; 136.332,60.132 136.332,60.64 ; 136.332,60.132 136.332,59.751 136.459,59.624 ; 136.332,60.64 136.713,60.64 ; 136.332,60.64 136.332,61.148 ; 136.332,61.148 136.713,61.148 ; 136.332,61.148 136.332,61.656 ; 136.332,61.656 136.713,61.656 ; 136.459,59.624 136.713,59.37 ; 136.459,59.624 136.713,59.624 ; 136.713,59.37 136.713,59.624 ; 136.713,59.37 136.967,59.116 ; 136.713,59.624 136.713,60.132 ; 136.713,59.624 137.221,59.624 ; 136.713,60.132 136.713,60.64 ; 136.713,60.132 137.221,60.132 ; 136.713,60.64 136.713,61.148 ; 136.713,60.64 137.221,60.64 ; 136.713,61.148 136.713,61.656 ; 136.713,61.148 137.221,61.148 ; 136.713,61.656 136.713,62.164 ; 136.713,61.656 137.221,61.656 ; 136.713,62.164 136.713,62.672 ; 136.713,62.164 137.221,62.164 ; 136.713,62.672 136.713,63.18 ; 136.713,62.672 137.221,62.672 ; 136.713,63.18 136.713,63.688 ; 136.713,63.18 137.221,63.18 ; 136.713,63.688 136.713,64.196 ; 136.713,63.688 137.221,63.688 ; 136.713,64.196 136.713,64.704 ; 136.713,64.196 137.221,64.196 ; 136.713,64.704 136.713,65.212 ; 136.713,64.704 137.221,64.704 ; 136.713,65.212 136.713,65.72 ; 136.713,65.212 137.221,65.212 ; 136.713,65.72 136.713,66.228 ; 136.713,65.72 137.221,65.72 ; 136.713,66.228 136.713,66.736 ; 136.713,66.228 137.221,66.228 ; 136.713,66.736 136.713,67.244 ; 136.713,66.736 137.221,66.736 ; 136.713,67.244 136.713,67.752 ; 136.713,67.244 137.221,67.244 ; 136.713,67.752 137.221,67.752 ; 136.713,67.752 137.221,68.26 ; 136.713,90.655 136.713,91.12 ; 136.713,91.12 136.713,91.628 ; 136.713,91.12 137.221,91.12 ; 136.713,91.628 136.713,92.136 ; 136.713,91.628 137.221,91.628 ; 136.713,92.136 136.713,92.644 ; 136.713,92.136 137.221,92.136 ; 136.713,92.644 136.713,93.152 ; 136.713,92.644 137.221,92.644 ; 136.713,93.152 137.221,93.152 ; 136.713,93.152 136.713,93.66 ; 136.713,93.66 137.221,93.66 ; 136.713,93.66 136.713,94.168 ; 136.713,94.168 137.221,94.168 ; 136.713,94.168 136.713,94.676 ; 136.713,94.676 137.221,94.676 ; 136.713,94.676 136.713,95.184 ; 136.713,95.184 137.221,95.184 ; 136.713,95.184 136.713,95.692 ; 136.713,95.692 137.221,95.692 ; 136.713,95.692 136.713,95.946 ; 136.713,95.946 137.221,95.946 ; 136.967,59.116 137.221,59.116 ; 136.967,59.116 137.221,58.862 ; 137.221,58.862 137.221,59.116 ; 137.221,58.862 137.475,58.608 ; 137.221,59.116 137.221,59.624 ; 137.221,59.116 137.729,59.116 ; 137.221,59.624 137.729,59.624 ; 137.221,59.624 137.221,60.132 ; 137.221,60.132 137.221,60.64 ; 137.221,60.132 137.729,60.132 ; 137.221,60.64 137.221,61.148 ; 137.221,60.64 137.729,60.64 ; 137.221,61.148 137.221,61.656 ; 137.221,61.148 137.729,61.148 ; 137.221,61.656 137.729,61.656 ; 137.221,61.656 137.221,62.164 ; 137.221,62.164 137.729,62.164 ; 137.221,62.164 137.221,62.672 ; 137.221,62.672 137.729,62.672 ; 137.221,62.672 137.221,63.18 ; 137.221,63.18 137.729,63.18 ; 137.221,63.18 137.221,63.688 ; 137.221,63.688 137.221,64.196 ; 137.221,63.688 137.729,63.688 ; 137.221,64.196 137.729,64.196 ; 137.221,64.196 137.221,64.704 ; 137.221,64.704 137.729,64.704 ; 137.221,64.704 137.221,65.212 ; 137.221,65.212 137.221,65.72 ; 137.221,65.212 137.729,65.212 ; 137.221,65.72 137.221,66.228 ; 137.221,65.72 137.729,65.72 ; 137.221,66.228 137.221,66.736 ; 137.221,66.228 137.729,66.228 ; 137.221,66.736 137.729,66.736 ; 137.221,66.736 137.221,67.244 ; 137.221,67.244 137.729,67.244 ; 137.221,67.244 137.221,67.752 ; 137.221,67.752 137.221,68.26 ; 137.221,67.752 137.729,67.752 ; 137.221,68.26 137.729,68.768 ; 137.221,68.26 137.729,68.26 ; 137.221,90.884 137.221,91.12 ; 137.221,90.884 137.457,91.12 ; 137.221,91.12 137.221,91.628 ; 137.221,91.12 137.457,91.12 ; 137.221,91.628 137.221,92.136 ; 137.221,91.628 137.729,91.628 ; 137.221,92.136 137.221,92.644 ; 137.221,92.136 137.729,92.136 ; 137.221,92.644 137.221,93.152 ; 137.221,92.644 137.729,92.644 ; 137.221,93.152 137.729,93.152 ; 137.221,93.152 137.221,93.66 ; 137.221,93.66 137.729,93.66 ; 137.221,93.66 137.221,94.168 ; 137.221,94.168 137.729,94.168 ; 137.221,94.168 137.221,94.676 ; 137.221,94.676 137.729,94.676 ; 137.221,94.676 137.221,95.184 ; 137.221,95.184 137.729,95.184 ; 137.221,95.184 137.221,95.692 ; 137.221,95.692 pad.@137.729,95.692 ; 137.221,95.692 137.221,95.946 ; 137.221,95.946 pad.@137.729,95.946 ; 137.43,85.055 cw(c138.451,84.095) 137.729,85.296 137.729,85.532 ; 137.43,85.055 137.43,85.532 ; 137.43,85.532 137.43,86.04 ; 137.43,85.532 137.729,85.532 ; 137.43,86.04 137.43,86.548 ; 137.43,86.04 137.729,86.04 ; 137.43,86.548 137.43,87.056 ; 137.43,86.548 pad.@137.729,86.548 ; 137.43,87.056 137.43,87.27 137.724,87.564 ; 137.43,87.056 137.729,87.056 ; 137.457,91.12 137.729,91.392 ; 137.475,58.608 137.729,58.354 ; 137.475,58.608 137.729,58.608 ; 137.724,87.564 137.729,87.564 ; 137.724,87.564 137.729,87.569 ; 137.729,58.354 137.983,58.1 ; 137.729,58.354 137.729,58.608 ; 137.729,58.608 137.729,59.116 ; 137.729,58.608 138.237,58.608 ; 137.729,59.116 137.729,59.624 ; 137.729,59.116 138.237,59.116 ; 137.729,59.624 137.729,60.132 ; 137.729,59.624 138.237,59.624 ; 137.729,60.132 137.729,60.64 ; 137.729,60.132 138.237,60.132 ; 137.729,60.64 137.729,61.148 ; 137.729,60.64 EC16.2@138.237,60.64 ; 137.729,61.148 137.729,61.656 ; 137.729,61.148 EC16.2@138.237,61.148 ; 137.729,61.656 138.237,61.656 ; 137.729,61.656 137.729,62.164 ; 137.729,62.164 138.237,62.164 ; 137.729,62.164 137.729,62.672 ; 137.729,62.672 138.237,62.672 ; 137.729,62.672 137.729,63.18 ; 137.729,63.18 137.729,63.688 ; 137.729,63.18 138.237,63.18 ; 137.729,63.688 137.729,64.196 ; 137.729,63.688 138.237,63.688 ; 137.729,64.196 137.729,64.704 ; 137.729,64.196 138.237,64.196 ; 137.729,64.704 138.237,64.704 ; 137.729,64.704 137.729,65.212 ; 137.729,65.212 137.729,65.72 ; 137.729,65.212 138.237,65.212 ; 137.729,65.72 137.729,66.228 ; 137.729,65.72 138.237,65.72 ; 137.729,66.228 137.729,66.736 ; 137.729,66.228 138.237,66.228 ; 137.729,66.736 138.237,66.736 ; 137.729,66.736 137.729,67.244 ; 137.729,67.244 138.237,67.244 ; 137.729,67.244 137.729,67.752 ; 137.729,67.752 137.729,68.26 ; 137.729,67.752 138.237,67.752 ; 137.729,68.26 137.729,68.768 ; 137.729,68.26 138.237,68.26 ; 137.729,68.768 138.237,69.276 ; 137.729,68.768 138.237,68.768 ; 137.729,85.532 137.729,86.04 ; 137.729,85.532 138.034,85.532 ; 137.729,86.04 138.071,86.04 ; 137.729,86.04 pad.@137.729,86.548 ; pad.@137.729,86.548 pad.@137.983,86.548 pad.@138.237,86.548 ; pad.@137.729,86.548 137.729,87.056 ; 137.729,87.056 137.729,87.564 ; 137.729,87.056 138.237,87.056 ; 137.729,87.564 138.237,87.564 ; 137.729,87.564 137.729,87.569 ; 137.729,91.392 137.729,91.628 ; 137.729,91.628 137.729,92.136 ; 137.729,91.628 137.993,91.628 ; 137.729,92.136 137.729,92.644 ; 137.729,92.136 138.237,92.136 ; 137.729,92.644 137.729,93.152 ; 137.729,92.644 138.237,92.644 ; 137.729,93.152 138.237,93.152 ; 137.729,93.152 137.729,93.66 ; 137.729,93.66 138.237,93.66 ; 137.729,93.66 137.729,94.168 ; 137.729,94.168 138.237,94.168 ; 137.729,94.168 137.729,94.676 ; 137.729,94.676 138.237,94.676 ; 137.729,94.676 137.729,95.184 ; 137.729,95.184 138.237,95.184 ; 137.729,95.184 pad.@137.729,95.692 ; pad.@137.729,95.692 pad.@138.237,95.692 ; pad.@137.729,95.692 pad.@137.729,95.946 ; pad.@137.729,95.946 pad.@138.237,95.946 ; 137.983,58.1 138.237,58.1 ; 137.983,58.1 138.11,57.973 138.11,57.592 ; 137.993,91.628 ccw(c138.772,90.524) 137.817,91.48 cw(c138.772,90.524) 137.993,91.628 ; 137.993,91.628 cw(c138.772,90.524) 137.997,91.631 ; 137.993,91.628 cw(c138.772,90.524) 137.997,91.631 ; 137.997,91.631 cw(c138.772,90.524) 138.237,91.765 ; 137.997,91.631 cw(c138.772,90.524) 138.237,91.765 ; 138.034,85.532 ccw(c138.999,85.717) 138.056,85.44 ; 138.034,85.532 cw(c138.999,85.717) 138.07,86.037 cw(c138.999,85.717) 138.071,86.04 ; 138.071,86.04 cw(c138.999,85.717) pad.@138.237,86.338 ; 138.11,50.48 138.237,50.48 ; 138.11,50.48 138.11,50.988 ; 138.11,50.48 138.11,50.226 138.237,50.099 ; 138.11,50.988 138.237,50.988 ; 138.11,50.988 138.11,51.496 ; 138.11,51.496 138.11,52.004 ; 138.11,51.496 138.237,51.496 ; 138.11,52.004 138.237,52.004 ; 138.11,52.004 138.11,52.512 ; 138.11,52.512 138.11,53.02 ; 138.11,52.512 138.237,52.512 ; 138.11,53.02 138.237,53.02 ; 138.11,53.02 138.11,53.528 ; 138.11,53.528 138.237,53.528 ; 138.11,53.528 138.11,54.036 ; 138.11,54.036 138.237,54.036 ; 138.11,54.036 138.11,54.544 ; 138.11,54.544 138.237,54.544 ; 138.11,54.544 138.11,55.052 ; 138.11,55.052 138.237,55.052 ; 138.11,55.052 138.11,55.56 ; 138.11,55.56 138.11,56.068 ; 138.11,55.56 138.237,55.56 ; 138.11,56.068 138.237,56.068 ; 138.11,56.068 138.11,56.576 ; 138.11,56.576 138.237,56.576 ; 138.11,56.576 138.11,57.084 ; 138.11,57.084 138.11,57.592 ; 138.11,57.084 138.237,57.084 ; 138.11,57.592 138.237,57.592 ; 138.232,88.072 138.237,88.077 ; 138.232,88.072 138.237,88.072 ; 138.237,50.099 138.364,49.972 ; 138.237,50.099 138.237,50.48 ; 138.237,50.48 138.745,50.48 ; 138.237,50.48 138.237,50.988 ; 138.237,50.988 138.745,50.988 ; 138.237,50.988 138.237,51.496 ; 138.237,51.496 138.237,52.004 ; 138.237,51.496 138.745,51.496 ; 138.237,52.004 138.745,52.004 ; 138.237,52.004 138.237,52.512 ; 138.237,52.512 138.237,53.02 ; 138.237,52.512 138.745,52.512 ; 138.237,53.02 138.745,53.02 ; 138.237,53.02 138.237,53.528 ; 138.237,53.528 138.237,54.036 ; 138.237,53.528 138.745,53.528 ; 138.237,54.036 138.237,54.544 ; 138.237,54.036 138.745,54.036 ; 138.237,54.544 138.237,55.052 ; 138.237,54.544 138.745,54.544 ; 138.237,55.052 138.237,55.56 ; 138.237,55.052 138.745,55.052 ; 138.237,55.56 138.237,56.068 ; 138.237,55.56 138.745,55.56 ; 138.237,56.068 138.745,56.068 ; 138.237,56.068 138.237,56.576 ; 138.237,56.576 138.745,56.576 ; 138.237,56.576 138.237,57.084 ; 138.237,57.084 138.237,57.592 ; 138.237,57.084 pad.@138.745,57.084 ; 138.237,57.592 138.745,57.592 ; 138.237,57.592 138.237,58.1 ; 138.237,58.1 138.745,58.1 ; 138.237,58.1 138.237,58.608 ; 138.237,58.608 138.237,59.116 ; 138.237,58.608 138.745,58.608 ; 138.237,59.116 138.237,59.624 ; 138.237,59.116 138.745,59.116 ; 138.237,59.624 138.745,59.624 ; 138.237,59.624 138.237,60.132 ; 138.237,60.132 138.731,60.132 EC16.2@138.745,60.132 ; 138.237,60.132 EC16.2@138.237,60.64 ; EC16.2@138.237,60.64 EC16.2@138.745,60.64 ; EC16.2@138.237,60.64 EC16.2@138.237,61.148 ; EC16.2@138.237,61.148 138.237,61.656 ; EC16.2@138.237,61.148 EC16.2@138.745,61.148 ; 138.237,61.656 138.745,61.656 ; 138.237,61.656 138.237,62.164 ; 138.237,62.164 138.745,62.164 ; 138.237,62.164 138.237,62.672 ; 138.237,62.672 138.745,62.672 ; 138.237,62.672 138.237,63.18 ; 138.237,63.18 138.237,63.688 ; 138.237,63.18 138.745,63.18 ; 138.237,63.688 138.237,64.196 ; 138.237,63.688 138.745,63.688 ; 138.237,64.196 138.237,64.704 ; 138.237,64.196 138.745,64.196 ; 138.237,64.704 138.745,64.704 ; 138.237,64.704 138.237,65.212 ; 138.237,65.212 138.237,65.72 ; 138.237,65.212 138.745,65.212 ; 138.237,65.72 138.237,66.228 ; 138.237,65.72 138.745,65.72 ; 138.237,66.228 138.237,66.736 ; 138.237,66.228 138.745,66.228 ; 138.237,66.736 138.745,66.736 ; 138.237,66.736 138.237,67.244 ; 138.237,67.244 138.745,67.244 ; 138.237,67.244 138.237,67.752 ; 138.237,67.752 138.237,68.26 ; 138.237,67.752 138.745,67.752 ; 138.237,68.26 138.237,68.768 ; 138.237,68.26 138.745,68.26 ; 138.237,68.768 138.237,69.276 ; 138.237,68.768 138.745,68.768 ; 138.237,69.276 138.745,69.276 ; 138.237,69.276 138.745,69.784 ; pad.@138.237,86.338 pad.@138.237,86.548 ; pad.@138.237,86.548 138.385,86.548 ; pad.@138.237,86.548 138.237,87.056 ; 138.237,87.056 138.237,87.07 ; 138.237,87.07 ccw(c139.634,87.183) 138.238,87.056 ccw(c139.634,87.183) 138.385,86.548 ; 138.237,87.07 cw(c139.634,87.183) 138.237,87.296 ; 138.237,87.296 cw(c139.634,87.183) 138.238,87.305 cw(c139.634,87.183) 138.285,87.564 ; 138.237,87.296 138.237,87.564 ; 138.237,87.564 138.237,88.072 ; 138.237,87.564 138.285,87.564 ; 138.237,88.072 138.237,88.077 ; 138.237,88.077 138.74,88.58 ; 138.237,91.765 cw(c138.772,90.524) 138.745,91.875 ; 138.237,91.765 cw(c138.772,90.524) 138.745,91.875 ; 138.237,91.765 138.237,92.136 ; 138.237,92.136 138.237,92.644 ; 138.237,92.136 138.745,92.136 ; 138.237,92.644 138.237,93.152 ; 138.237,92.644 138.745,92.644 ; 138.237,93.152 138.745,93.152 ; 138.237,93.152 138.237,93.66 ; 138.237,93.66 138.745,93.66 ; 138.237,93.66 138.237,94.168 ; 138.237,94.168 138.745,94.168 ; 138.237,94.168 138.237,94.676 ; 138.237,94.676 pad.@138.745,94.676 ; 138.237,94.676 138.237,95.184 ; 138.237,95.184 pad.@138.745,95.184 ; 138.237,95.184 pad.@138.237,95.692 ; pad.@138.237,95.692 138.618,95.692 ; pad.@138.237,95.692 pad.@138.237,95.946 ; pad.@138.237,95.946 138.364,95.946 138.618,95.692 ; 138.364,49.972 138.745,49.972 ; 138.364,49.972 138.745,49.591 ; 138.618,95.692 138.745,95.565 ; 138.74,88.58 138.745,88.585 ; 138.74,88.58 138.745,88.58 ; 138.745,49.591 138.745,49.972 ; 138.745,49.591 138.872,49.464 139.253,49.464 ; 138.745,49.972 138.745,50.48 ; 138.745,49.972 139.253,49.972 ; 138.745,50.48 138.745,50.988 ; 138.745,50.48 139.253,50.48 ; 138.745,50.988 138.745,51.496 ; 138.745,50.988 139.253,50.988 ; 138.745,51.496 138.745,52.004 ; 138.745,51.496 139.253,51.496 ; 138.745,52.004 138.745,52.512 ; 138.745,52.004 139.253,52.004 ; 138.745,52.512 138.745,53.02 ; 138.745,52.512 139.253,52.512 ; 138.745,53.02 138.745,53.528 ; 138.745,53.02 139.253,53.02 ; 138.745,53.528 138.745,54.036 ; 138.745,53.528 139.253,53.528 ; 138.745,54.036 138.745,54.544 ; 138.745,54.036 139.253,54.036 ; 138.745,54.544 138.745,55.052 ; 138.745,54.544 139.253,54.544 ; 138.745,55.052 138.745,55.56 ; 138.745,55.052 139.253,55.052 ; 138.745,55.56 138.745,56.068 ; 138.745,55.56 139.253,55.56 ; 138.745,56.068 138.745,56.576 ; 138.745,56.068 139.253,56.068 ; 138.745,56.576 139.253,56.576 ; 138.745,56.576 pad.@138.745,57.084 ; pad.@138.745,57.084 138.745,57.592 ; pad.@138.745,57.084 139.253,57.084 ; 138.745,57.592 138.745,58.1 ; 138.745,57.592 139.253,57.592 ; 138.745,58.1 138.745,58.608 ; 138.745,58.1 139.253,58.1 ; 138.745,58.608 138.745,59.116 ; 138.745,58.608 139.253,58.608 ; 138.745,59.116 138.745,59.624 ; 138.745,59.116 139.253,59.116 ; 138.745,59.624 EC16.2@138.745,60.132 ; 138.745,59.624 139.253,59.624 ; EC16.2@138.745,60.132 EC16.2@138.745,60.64 ; EC16.2@138.745,60.132 EC16.2@139.253,60.132 ; EC16.2@138.745,60.64 EC16.2@138.745,61.148 ; EC16.2@138.745,60.64 EC16.2@139.253,60.64 ; EC16.2@138.745,61.148 138.745,61.656 ; EC16.2@138.745,61.148 EC16.2@139.253,61.148 ; 138.745,61.656 138.745,62.164 ; 138.745,61.656 139.253,61.656 ; 138.745,62.164 139.253,62.164 ; 138.745,62.164 138.745,62.672 ; 138.745,62.672 139.253,62.672 ; 138.745,62.672 138.745,63.18 ; 138.745,63.18 138.745,63.688 ; 138.745,63.18 139.253,63.18 ; 138.745,63.688 138.745,64.196 ; 138.745,63.688 139.253,63.688 ; 138.745,64.196 138.745,64.704 ; 138.745,64.196 139.253,64.196 ; 138.745,64.704 139.253,64.704 ; 138.745,64.704 138.745,65.212 ; 138.745,65.212 138.745,65.72 ; 138.745,65.212 139.253,65.212 ; 138.745,65.72 138.745,66.228 ; 138.745,65.72 139.253,65.72 ; 138.745,66.228 138.745,66.736 ; 138.745,66.228 139.253,66.228 ; 138.745,66.736 139.253,66.736 ; 138.745,66.736 138.745,67.244 ; 138.745,67.244 139.253,67.244 ; 138.745,67.244 138.745,67.752 ; 138.745,67.752 138.745,68.26 ; 138.745,67.752 139.253,67.752 ; 138.745,68.26 138.745,68.768 ; 138.745,68.26 139.253,68.26 ; 138.745,68.768 138.745,69.276 ; 138.745,68.768 138.745,69.276 ; 138.745,68.768 139.253,68.768 ; 138.745,69.276 138.745,69.784 ; 138.745,69.276 138.745,69.784 ; 138.745,69.276 139.253,69.276 ; 138.745,69.784 139.253,69.784 ; 138.745,69.784 138.745,70.292 ; 138.745,70.292 138.745,70.419 139.126,70.8 ; 138.745,70.292 139.253,70.292 ; 138.745,88.267 cw(c139.634,87.183) 138.905,88.38 ; 138.745,88.267 138.745,88.58 ; 138.745,88.58 138.745,88.585 ; 138.745,88.58 138.884,88.58 ; 138.745,88.585 138.822,88.662 ; 138.745,91.875 cw(c138.772,90.524) 138.772,91.876 ; 138.745,91.875 cw(c138.772,90.524) 138.772,91.876 ; 138.745,91.875 138.745,92.136 ; 138.745,92.136 138.745,92.644 ; 138.745,92.136 139.253,92.136 ; 138.745,92.644 138.745,93.152 ; 138.745,92.644 139.253,92.644 ; 138.745,93.152 139.253,93.152 ; 138.745,93.152 138.745,93.66 ; 138.745,93.66 139.253,93.66 ; 138.745,93.66 138.745,94.168 ; 138.745,94.168 139.253,94.168 ; 138.745,94.168 pad.@138.745,94.676 ; pad.@138.745,94.676 139.253,94.676 ; pad.@138.745,94.676 pad.@138.745,95.184 ; pad.@138.745,95.184 138.745,95.565 ; pad.@138.745,95.184 pad.@139.126,95.184 ; 138.745,95.565 pad.@139.126,95.184 ; 138.772,91.876 139.253,91.876 ; 138.822,88.662 ccw(c139.634,89.215) 138.884,88.58 ; 139.126,70.8 139.253,70.927 ; 139.126,70.8 139.253,70.8 ; pad.@139.126,95.184 pad.@139.253,95.057 ; 139.253,49.464 139.253,49.972 ; 139.253,49.464 139.761,49.464 ; 139.253,49.972 139.253,50.48 ; 139.253,49.972 139.761,49.972 ; 139.253,50.48 139.253,50.988 ; 139.253,50.48 139.761,50.48 ; 139.253,50.988 139.253,51.496 ; 139.253,50.988 139.761,50.988 ; 139.253,51.496 139.253,52.004 ; 139.253,51.496 139.761,51.496 ; 139.253,52.004 139.253,52.512 ; 139.253,52.004 139.761,52.004 ; 139.253,52.512 139.253,53.02 ; 139.253,52.512 139.761,52.512 ; 139.253,53.02 139.253,53.528 ; 139.253,53.02 139.761,53.02 ; 139.253,53.528 139.253,54.036 ; 139.253,53.528 139.761,53.528 ; 139.253,54.036 139.253,54.544 ; 139.253,54.036 139.761,54.036 ; 139.253,54.544 139.253,55.052 ; 139.253,54.544 139.761,54.544 ; 139.253,55.052 139.253,55.56 ; 139.253,55.052 139.761,55.052 ; 139.253,55.56 139.253,56.068 ; 139.253,55.56 139.761,55.56 ; 139.253,56.068 139.253,56.576 ; 139.253,56.068 139.761,56.068 ; 139.253,56.576 139.253,57.084 ; 139.253,56.576 139.761,56.576 ; 139.253,57.084 139.253,57.592 ; 139.253,57.084 139.761,57.084 ; 139.253,57.592 139.253,58.1 ; 139.253,57.592 139.761,57.592 ; 139.253,58.1 139.253,58.608 ; 139.253,58.1 139.761,58.1 ; 139.253,58.608 139.253,59.116 ; 139.253,58.608 139.761,58.608 ; 139.253,59.116 139.253,59.624 ; 139.253,59.116 139.761,59.116 ; 139.253,59.624 EC16.2@139.253,60.132 ; 139.253,59.624 139.761,59.624 ; EC16.2@139.253,60.132 139.761,60.132 ; EC16.2@139.253,60.132 EC16.2@139.253,60.64 ; EC16.2@139.253,60.64 139.72,60.64 ; EC16.2@139.253,60.64 EC16.2@139.253,61.148 ; EC16.2@139.253,61.148 139.253,61.656 ; EC16.2@139.253,61.148 139.74,61.148 ; 139.253,61.656 139.253,62.164 ; 139.253,61.656 139.761,61.656 ; 139.253,62.164 139.253,62.672 ; 139.253,62.164 139.761,62.164 ; 139.253,62.672 139.253,63.18 ; 139.253,62.672 139.761,62.672 ; 139.253,63.18 139.253,63.688 ; 139.253,63.18 139.761,63.18 ; 139.253,63.688 139.253,64.196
